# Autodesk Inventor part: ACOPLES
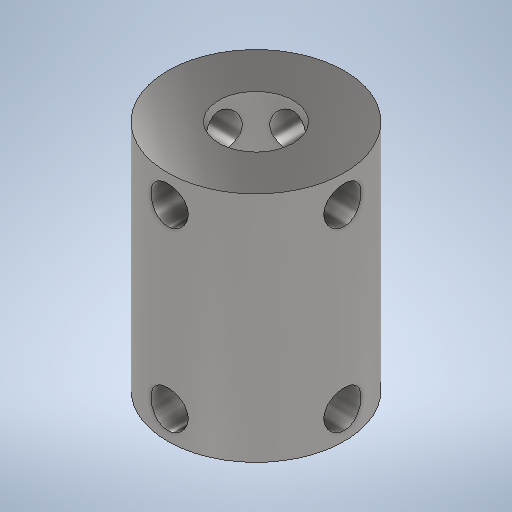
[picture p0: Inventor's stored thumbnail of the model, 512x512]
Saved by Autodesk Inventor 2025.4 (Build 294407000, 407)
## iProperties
Created: 2026-04
Part Number: ACOPLES
Material: Stainless Steel
Document SubType Name: Modeling
Designer: PC
Density: 8 g/cm^3
Appearance: Semi-Polished
Author: PC
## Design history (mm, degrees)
sketch "Sketch1"
  geometry: C1 r 9.5 at (0, 0); 1 further point
  constraints: 1 centre point, 1 coincident
  dimensions: "d0" = 19 diameter of C1
extrude "Extrusion1" new body sketch "Sketch1" distance "d1" = 25; taper "d2" = 0 deg
sketch "Sketch2"
  geometry: C1 r 4 at (0, 0); 1 further point
  constraints: 1 centre point, 1 coincident
  dimensions: "d3" = 8 diameter of C1
extrude "Extrusion2" cut sketch "Sketch2" extent not by distance; stored distance "d4" = 0; taper "d5" = 0 deg
workplane "Work Plane1"
sketch "Sketch3"
  geometry: L1 (25, -9.5)-(25, 9.5) reference; L2 (0, -9.5)-(0, 9.5) reference; C1 r 2 at (22, 0); C2 r 2 at (3, 0); 1 further point
  constraints: 2 centre point
  dimensions: "d7" = 4 diameter of C1; "d8" = 4 diameter of C2; "d9" = 3 distance from line of L1 C1.centre; "d10" = 3 distance from line of L2 C2.centre
extrude "Extrusion3" cut sketch "Sketch3" extent not by distance; stored distance "d11" = 0; taper "d12" = 0 deg
workplane "Work Plane2"
sketch "Sketch4"
  geometry: L1 (9.5, 25)-(-9.5, 25) reference; L2 (9.5, 0)-(-9.5, 0) reference; C1 r 2 at (0, 22); C2 r 2 at (0, 3); 1 further point
  constraints: 2 centre point
  dimensions: "d14" = 4 diameter of C1; "d15" = 4 diameter of C2; "d16" = 3 distance from line of L1 C1.centre; "d17" = 3 distance from line of L2 C2.centre
extrude "Extrusion4" cut sketch "Sketch4" extent not by distance; stored distance "d18" = 0; taper "d19" = 0 deg
body "Solid1"
other parameters: "d6" = 9.5, "d13" = 9.5
